// Mitsubishi GX Works2 project: 41.将Kn存到Dn（循环+变址）   PLC: FX3U/FX3UC

PROGRAM MAIN
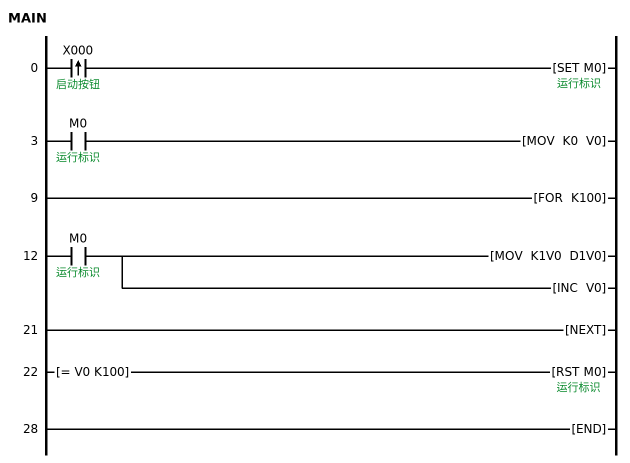
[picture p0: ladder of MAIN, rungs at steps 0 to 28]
0     LDP     X000  ; 启动按钮
      SET     M0  ; 运行标识
3     LD      M0  ; 运行标识
      MOV     K0 V0
9     FOR     K100
12    LD      M0  ; 运行标识
      MOV     K1V0 D1V0
      INC     V0
21    NEXT
22    LD=     V0 K100
      RST     M0  ; 运行标识
28    END
END_PROGRAM
